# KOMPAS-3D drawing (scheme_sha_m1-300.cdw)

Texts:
  Шкаф автоматики   Схема электрическая соединений
  Симоненко Е.Н.
  ЗАО "ЭТК"
  Текст на чертеже
  Размерные надписи
  Шероховатость
  Линия-выноска #1
  Линия-выноска #2
  Линия-выноска #3
  Отклонения формы и база
  Заголовок таблицы
  Ячейка таблицы
  Стрелка вида
  Обозначение изменения
  Фигурная скобка
  Номер узла
  Марка координационной оси
  VRCB
  Выносная надпись
  Обозначение узла
  Марка/позиционное обозначение с линией-выноской
  Марка/позиционное обозначение на линии
  Марка/позиционное обозначение без линии-выноски
  Без имени
  "Рег. ГВС"
  SF3
  SF4
  SF5
  SF6
  SF2
  "Кл. ПО"
  "Рег. ОТ"
  "Рег. ПД"
  "Розетка"
  "МАСТЕР
  Земля
  SF8
  "Осве-
  щение"
  HLG
  Symbol
  HLR
  "Обобщенный
  сигнал  аварии"
  SF9
  "Резерв"
  SF1
  "Общий"
  ХВ1
  Конт.
  Разъём
  Адрес
  МАСТЕР Т-300v1
  РП14А-30 Г6
  Разъем
  SA1/ I /4
  SA2/ I /4
  SA3/ I /4
  SA4/ I /4
  ХТ1/45
  HLR/F1
  SF2/2
  SA4/ II /4
  SA3/ II /4
  SA2/ II /4
  SA1/ II /4
  ХТ1.2 силовой / - 26
  Цепь
  Управление насосом
  № 1 ХВС
  Фаза авт.
  МП авт.
  № 2 ХВС
  № 3 ХВС
  № 4 ХВС
  № 1 ГВС
  № 2 ГВС
  № 3 ГВС
  № 1 ЦНО
  № 2 ЦНО
  № 3 ЦНО
  № 1 ПНО
  № 2 ПНО
  ДРН
  Управление клапаном
  подпитки отопления
  (Кл. ПО)
  Фаза ручн.
  Откр ПО
  Закр ПО
  Ноль
  регулятора ГВС
  (Рег. ГВС)
  Закр РГВС
  Откр РГВС
  регулятора отопления
  (Рег. ОТ)
  Закр РОТ
  Откр РОТ
  регулятора перепада
  давления
  (Рег. ПД)
  Закр РПД
  Откр РПД
  ХТ2.1 слаботочный / - 35
  ДПД ГВС1
  ДПД ГВС2
  ДПД ГВС3
  Расширитель-
  ный  бак
  общий
  макс. уровень
  мин. уровень
  ДПД ХВС1
  ДПД ХВС2
  ДПД ХВС3
  Дренаж
  ЭКМ ЦНО
  ЭКМ ХВС
  ДПД ХВС4
  ДПД ДРН
  макс .уровень
  ЭКМ ГВС
  РП14А-30 Ш6
  ТпрТС
  ХТ2.2  слаботочный /- 35
  Tahoma
  ТобрТС
  ТпрОТ
  ТобрОТ
  Тнв
  ТпрГВС
  Рпр1
  Робр1
  Рпр1вх
  Gтс
  Контроль двери
  Контроль воды
  ДПД ЦНО3
  ДПД ЦНО2
  ДПД ЦНО1
  ДПД ПНО1
  ДПД ПНО2
  ХВ3
  Фаза
  (от АВР)
  ХТ1.1 силовой / - 26
  Автомат
  Резерв
  ХВ2.1
  Примечание: На маркировке двухуровневых клемм
  клеммников ХТ1 и ХТ2 нечётному номеру контакта
  соответствует нижний, чётному - верхний контакт.
  ХТ1/49
  ХТ1/42
  ХВ2.2
  ХВ4
  ХВ5
  ХВ6
  ХВ7
  ХВ8
  ХВ9
  Розетка
  Коммутация цепей переключателя SA
  вид со стороны монтажа
  "Авт."
  "0ткл."
  "Ручн."
  SA1
  Дверца шкафа автоматики
  ХТ1/27
  ХТ1/35
  ХТ1/39
  SA2
  SA3
  SA4
  ХТ1/31
  QF7
  CONTINUOUS0
  Стили документа
  Шкаф автоматики
  Схема электрическая
  соединений
  Никулов Н.Ю.
  ООО
  "ЭТК-Прибор"
  типа ША М1-300
  ШКАФ АВТОМАТИКИ
  "Мастер Т-300v1" (ШАМ1-300)
  Схема электрическая соединений
  Мерекин С.А.
  ЗАО "Электротехническая
  компания"
Dimensions and other numbers on the sheet: 7; 1; 2; 16А; 3; 4; 5; 6; 8; 9; 10; 11; 12; 13; 14; 15; 16; 17; 18; 19; 20; 21; 22; 23; 24; 25; 26; 27; 28; 29; 30; 31; 32; 33; 34; 35; 36; 37; 38; 39; 40; 41; 42; 43; 44; 45; 46; 47; 48; 49; 50; 51; 52; 53; 54; 55; 57; 58; 56; 59; 60; 61; 62; 63; 64; 65; 66; 67; 68; 69; 70; 0,3; 0,2; 0,5; 0,4; 1:1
